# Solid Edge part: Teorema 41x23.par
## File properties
Title: Teorema R 41x23
Author: DESYS
Template: Iso Part.par
Last saved by: i.fialdini
Revision: 33
Application: Solid Edge
Tipo di contenuto documento: 0
Accuracy: 0.990
Document Number: 8031/R-41x23
Revision: 0
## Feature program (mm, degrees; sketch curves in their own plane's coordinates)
sketch for "unnamed Protrusion 1" plane through (10.8674, 10.8674, 0) normal (0, 0, 1) x-axis (1, 0, 0)
  line (-215.8674, 104.1326) -> (194.1326, 104.1326)
  line (194.1326, 104.1326) -> (194.1326, -125.8674)
  line (194.1326, -125.8674) -> (-215.8674, -125.8674)
  line (-215.8674, -125.8674) -> (-215.8674, 104.1326)
  dimension (linear) = 194.1326
  dimension (linear) = 215.8674
extrude "unnamed Protrusion 1" add finite 140 along -normal
sketch for "ScavoEstrusione_1" plane through (0, 0, 0) normal (0, 0, 1) x-axis (1, 0, 0)
  line (-195, -105) -> (70, -105)
  line (70, -105) -> (70, 105)
  line (70, 105) -> (-195, 105)
  line (-195, 105) -> (-195, -105)
extrude "ScavoEstrusione_1" cut finite 90 along -normal
draft "Spoglia_1"  Angles1 = 20 deg
sketch for "ScavoEstrusione_2" plane through (0, 0, -140) normal (0, 0, -1) x-axis (1, 0, 0)
  line (-165, -75) -> (-165, 75)
  line (-165, 75) -> (185, 75)
  line (185, 75) -> (185, -75)
  line (185, -75) -> (-65, -75)
  line (-65, -75) -> (-65, -105)
  line (-65, -105) -> (-135, -105)
  line (-135, -105) -> (-135, -75)
  line (-135, -75) -> (-165, -75)
  dimension (linear) = 65
  dimension (linear) = 165
  dimension (linear) = 165
  dimension (linear) = 135
  dimension (linear) = 65
extrude "ScavoEstrusione_2" cut finite 40 along -normal
sketch for "ScavoEstrusione_3" plane through (0, 0, -140) normal (0, 0, -1) x-axis (1, 0, 0)
  line (80, -75) -> (185, -75)
  line (185, -75) -> (185, 75)
  line (185, 75) -> (80, 75)
  line (80, 75) -> (80, -75)
  dimension (linear) = 185
extrude "ScavoEstrusione_3" cut finite 128 along -normal
sketch for "ScavoEstrusione_5" plane through (0, 0, 0) normal (0, 0, 1) x-axis (1, 0, 0)
  line (69.7941, -105) -> (69.7941, 105)
  line (69.7941, 105) -> (195, 105)
  line (195, 105) -> (195, -105)
  line (195, -105) -> (69.7941, -105)
extrude "ScavoEstrusione_5" cut finite 3 along -normal
sketch for "ScavoEstrusione_12" #1 plane through (0, 0, -140) normal (0, 0, -1) x-axis (1, 0, 0)
  circle centre (-195, 105) radius 5
sketch for "ScavoEstrusione_12" #2 plane through (0, 0, -140) normal (0, 0, -1) x-axis (1, 0, 0)
  circle centre (190, 105) radius 5
sketch for "ScavoEstrusione_12" #3 plane through (0, 0, -140) normal (0, 0, -1) x-axis (1, 0, 0)
  circle centre (190, -105) radius 5
sketch for "ScavoEstrusione_12" #4 plane through (0, 0, -140) normal (0, 0, -1) x-axis (1, 0, 0)
  circle centre (-190, -100) radius 5
extrude "ScavoEstrusione_12" cut finite 50 along -normal
sketch for "ScavoEstrusione_13" plane through (0, 115, -70) normal (0, 1, 0) x-axis (1, 0, 0)
  circle centre (-100.8474, 46.913) radius 8.087
extrude "ScavoEstrusione_13" cut finite 70 along -normal
sketch for "ProtrusioneEstrusa_2" plane through (-38.9735, 18.5265, -100) normal (0, 0, -1) x-axis (1, 0, 0)
  circle centre (-25.0152, 16.0538) radius 32.5
extrude "ProtrusioneEstrusa_2" add finite 35 along +normal
sketch for "ScavoEstrusione_14" plane through (-48.6205, 2.3315, -135) normal (0, 0, -1) x-axis (1, 0, 0)
  circle centre (-15.3681, -0.1443) radius 22.5676
extrude "ScavoEstrusione_14" cut finite 525 along -normal
sketch for "ScavoEstrusione_15" plane through (132.397, 0, -3) normal (0, 0, 1) x-axis (1, 0, 0)
  circle centre (-2.397, 0) radius 18
  dimension (linear) = 2.397
extrude "ScavoEstrusione_15" cut finite 1855 along -normal
sketch for "unnamed Cutout 1" plane through (0, 115, -70) normal (0, 1, 0) x-axis (-1, 0, 0)
  arc centre (-135.9022, 12.5) radius 14.0978 from (-142.4212, 0) to (-141.9773, 25.2216) cw
  line (-141.9773, 25.2216) -> (-122.5788, 25)
  arc centre (-129.0978, 12.5) radius 14.0978 from (-122.5788, 0) to (-122.5788, 25) ccw
  line (-142.4212, 0) -> (-122.5788, 0)
  dimension (linear) = 141.9773
  dimension (linear) = 142.4212
extrude "unnamed Cutout 1" cut to key point along -normal
sketch for "unnamed Cutout 2" plane through (-47.9412, 0, -90) normal (0, 0, 1) x-axis (-1, 0, 0)
  circle centre (16.0474, -2.4758) radius 29.0768
extrude "unnamed Cutout 2" cut finite 2 along -normal
fillet "unnamed Round 1"
sketch for "ScavoEstrusione_21" plane through (0, 0, -140) normal (0, 0, -1) x-axis (-1, 0, 0)
  line (-80, 75) -> (-80, 95)
  line (-80, 95) -> (-185, 95)
  line (-185, 75) -> (-185, 95)
  line (-80, 75) -> (-185, 75)
extrude "ScavoEstrusione_21" cut finite 110 along -normal
draft "Spoglia_2"  Angles1 = 10 deg
sketch for "unnamed Cutout 3" plane through (0, 2.3338, -70) normal (0, -1, 0) x-axis (-1, 0, 0)
  line (-185, 70) -> (-78, 70)
  line (-78, 70) -> (-90.0751, -43)
  line (-90.0751, -43) -> (-165.0751, -43)
  line (-165.0751, -43) -> (-185, 70)
  dimension (linear) = 90.0751
extrude "unnamed Cutout 3" cut finite 87.67 along -normal
fillet "Rotondo_6" radius 10
fillet "Rotondo_9" radius 5
fillet "Rotondo_12" radius 2
fillet "Rotondo_13" radius 2
fillet "Rotondo_14" radius 2
fillet "Rotondo_15" radius 2
fillet "Rotondo_16" radius 2
fillet "Rotondo_17" radius 1
fillet "Rotondo_18" radius 7.5
fillet "Rotondo_19" radius 0.5
fillet "Rotondo_20" radius 0.5
fillet "Rotondo_21" radius 0.5
fillet "Rotondo_22" radius 1  Radii2 = 0.5 mm
fillet "unnamed Round 2"
replace surface "unnamed ReplaceSurface 1"
replace surface "unnamed ReplaceSurface 2"
fillet "Rotondo_24" radius 2
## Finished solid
Body 1: solid body, 161 faces, 341 edges, 181 vertices.
  Faces by surface: cylinder 72, plane 35, blend 25, torus 25, sphere 4
  Edges by curve: line 139, circle 129, ellipse 56, intersection 17
Bounding box of the edges (mm; curved faces can reach further): 410.000 x 230.000 x 140.000, from (-205, -115, -140) to (205, 115, 0).
Cylindrical faces by radius (mm): R0.5 x18, R1 x5, R2 x18, R5 x13, R7.5 x4, R8.087 x1, R10 x8, R14.0978 x2, R18 x1, R22.5676 x1, R32.5 x1
Toroidal faces (ring radius, tube radius in mm): R1.5 r0.5 x2, R2.5 r7.5 x4, R5.5 r0.5 x4, R8.587 r0.5 x1, R9.5 r0.5 x4, R14.5978 r0.5 x4, R20 r2 x2, R24.5676 r2 x1, R25.5676 r3 x1, R30.5 r2 x1, R31.9052 r3 x1
Spherical faces by radius (mm): R2 x4
Planar faces by outward normal: +x 2, +y 1, +z 5, -x 2, -y 3, -z 9, oblique 13
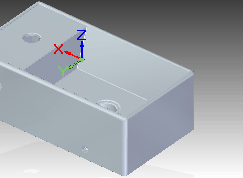
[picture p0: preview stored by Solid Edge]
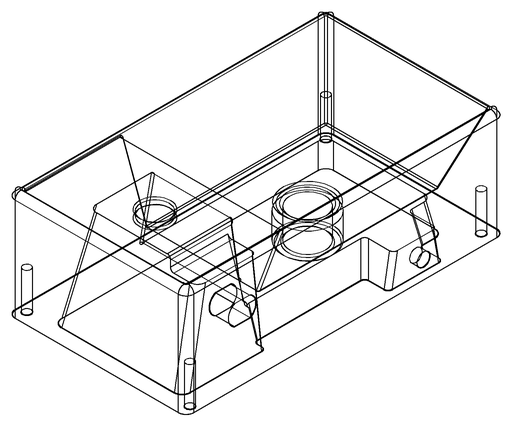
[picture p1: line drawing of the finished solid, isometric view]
